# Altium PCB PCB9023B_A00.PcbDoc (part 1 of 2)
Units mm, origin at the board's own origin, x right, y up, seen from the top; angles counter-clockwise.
Board outline 30 x 45 mm, 4 copper layers (Top Layer, Signal Layer 2, Signal Layer 3, Bottom Layer), stack 1.606 mm thick; 75 components, 84 nets, 313 pads, 395 vias.
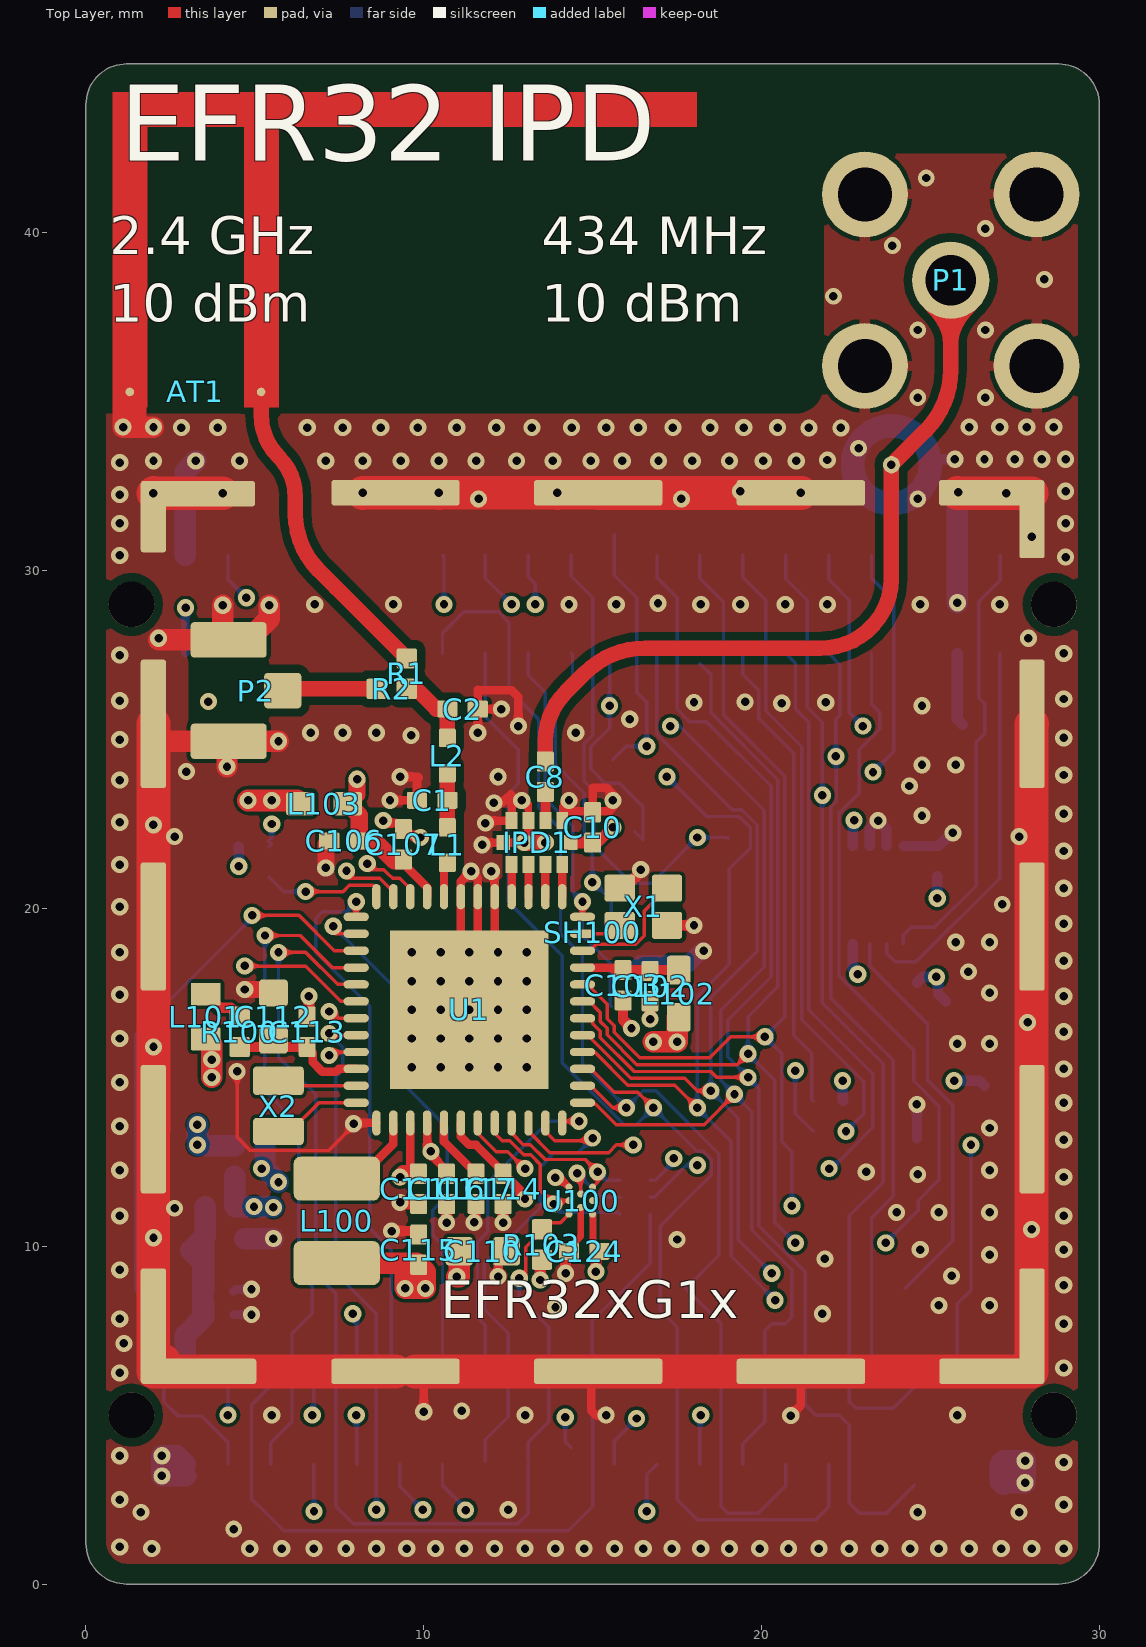
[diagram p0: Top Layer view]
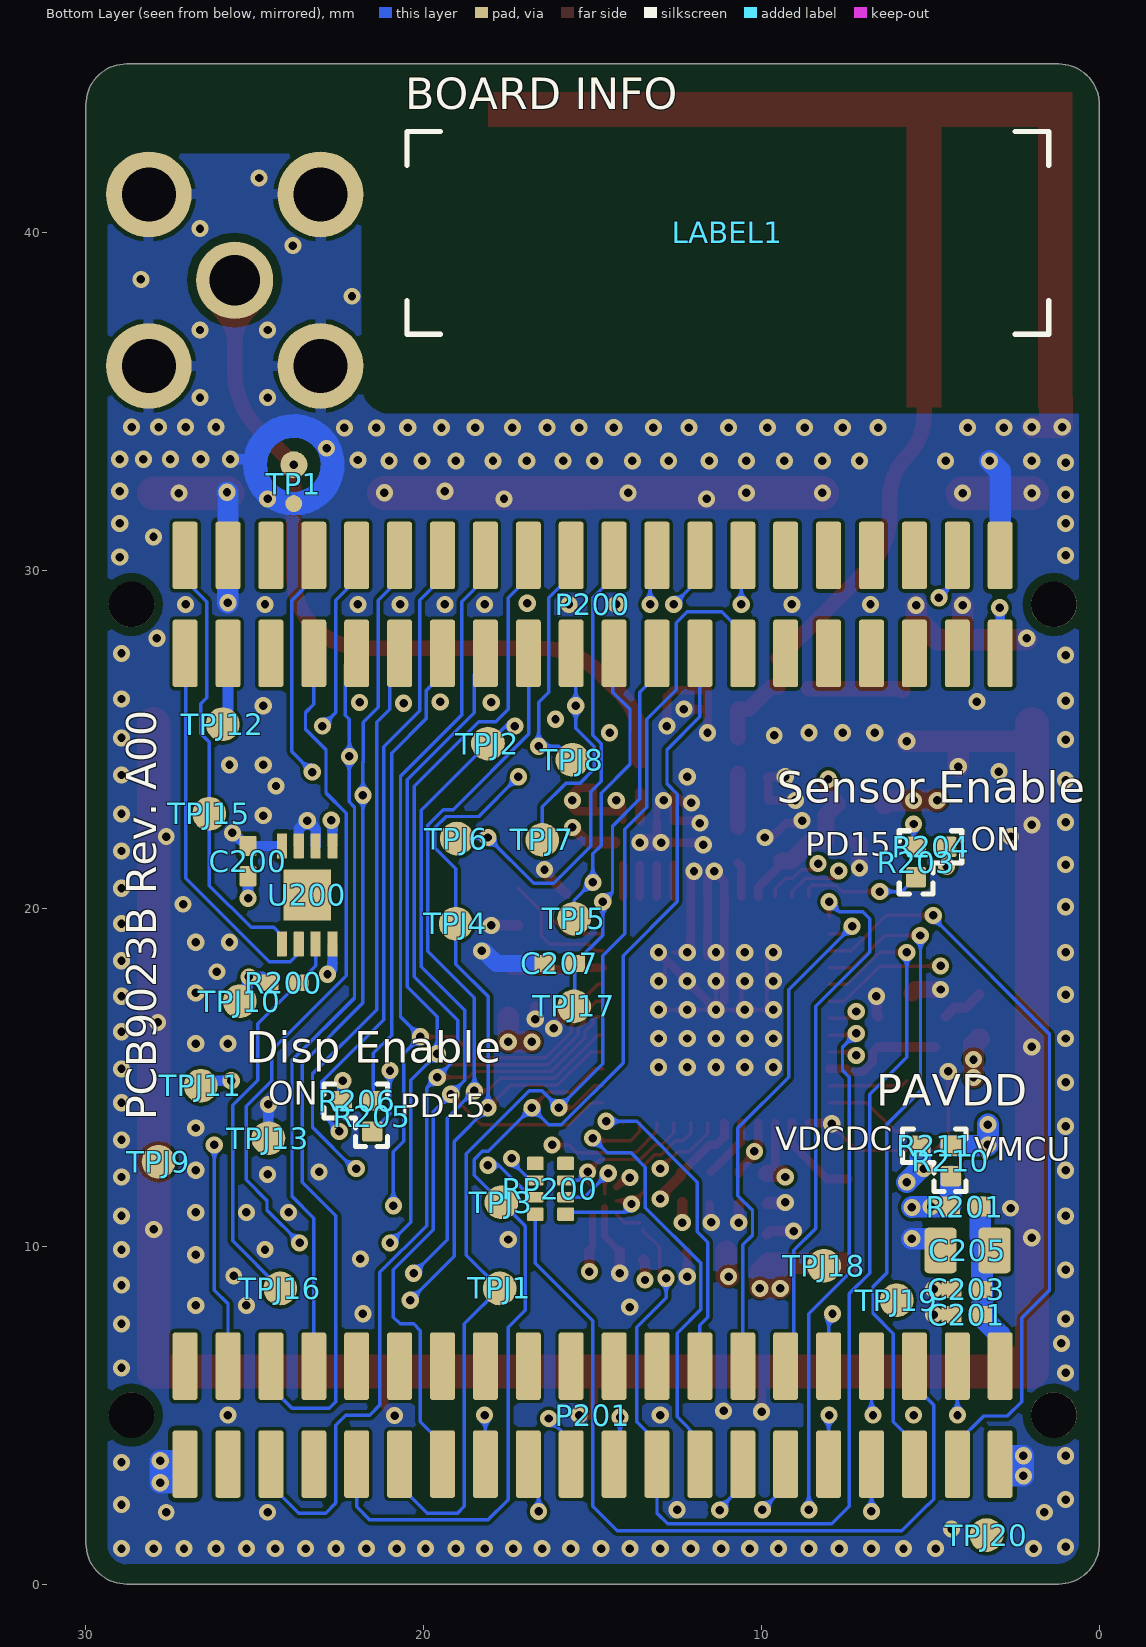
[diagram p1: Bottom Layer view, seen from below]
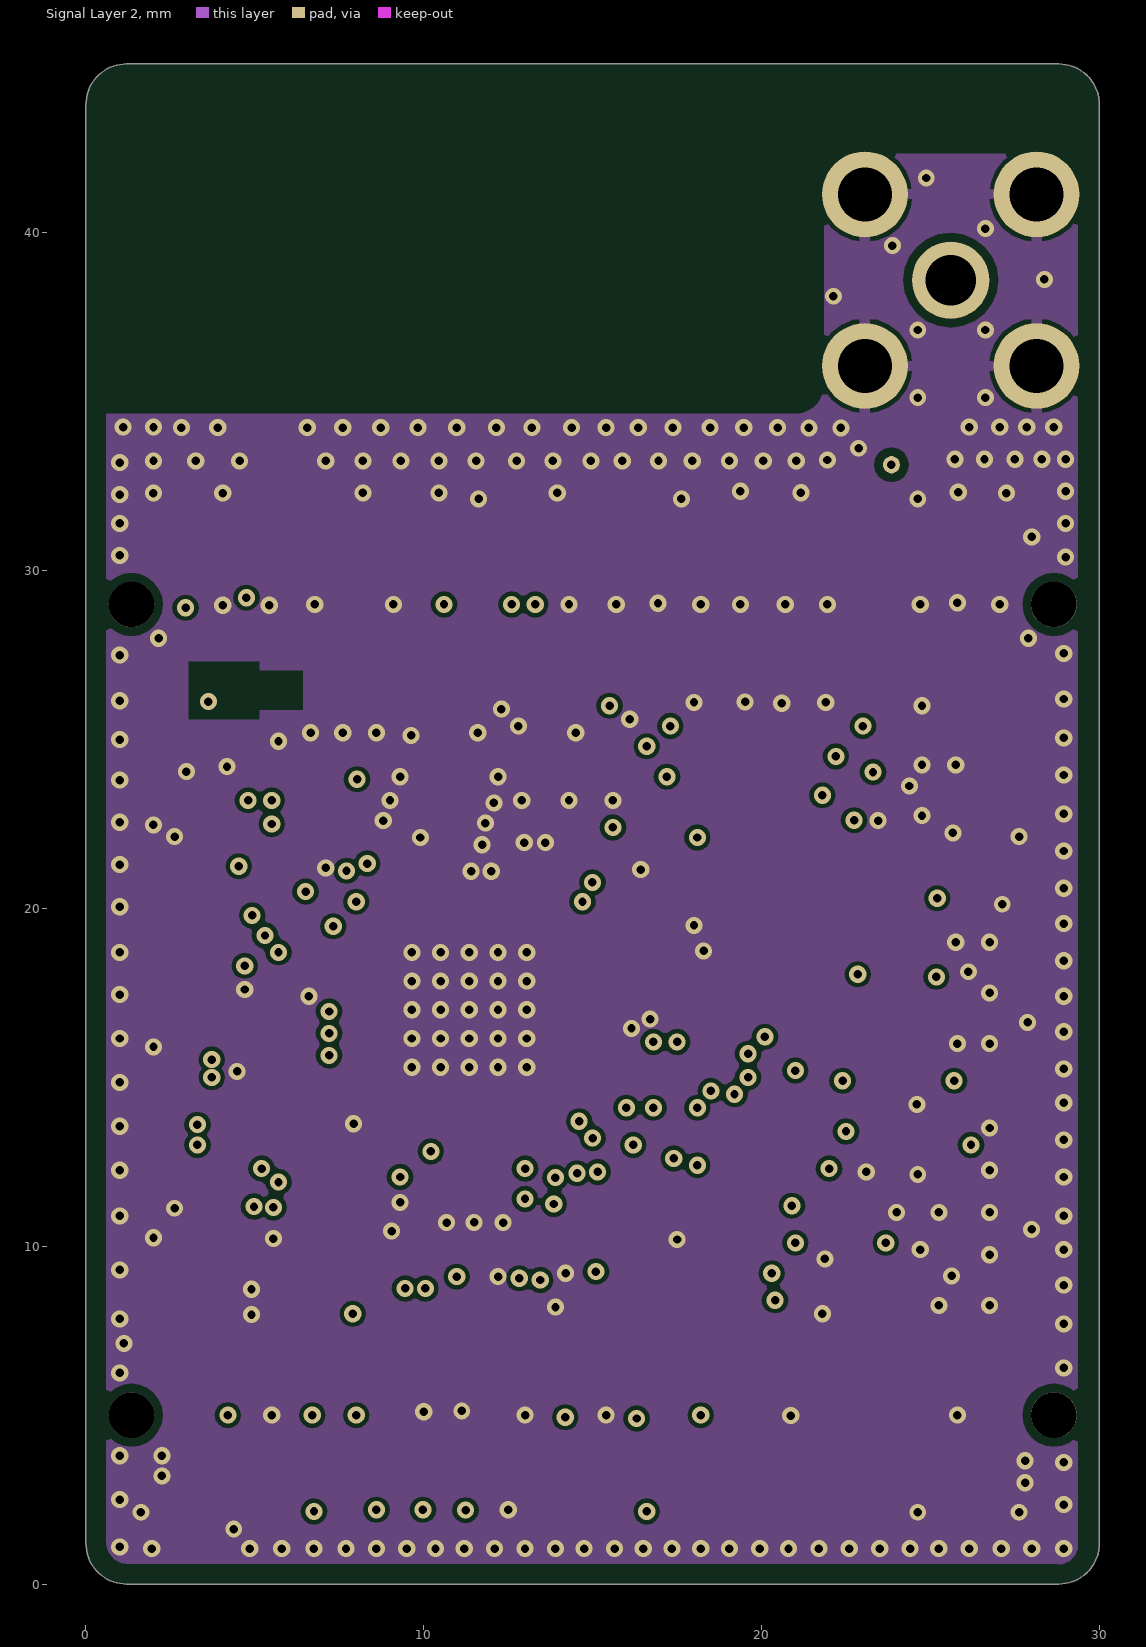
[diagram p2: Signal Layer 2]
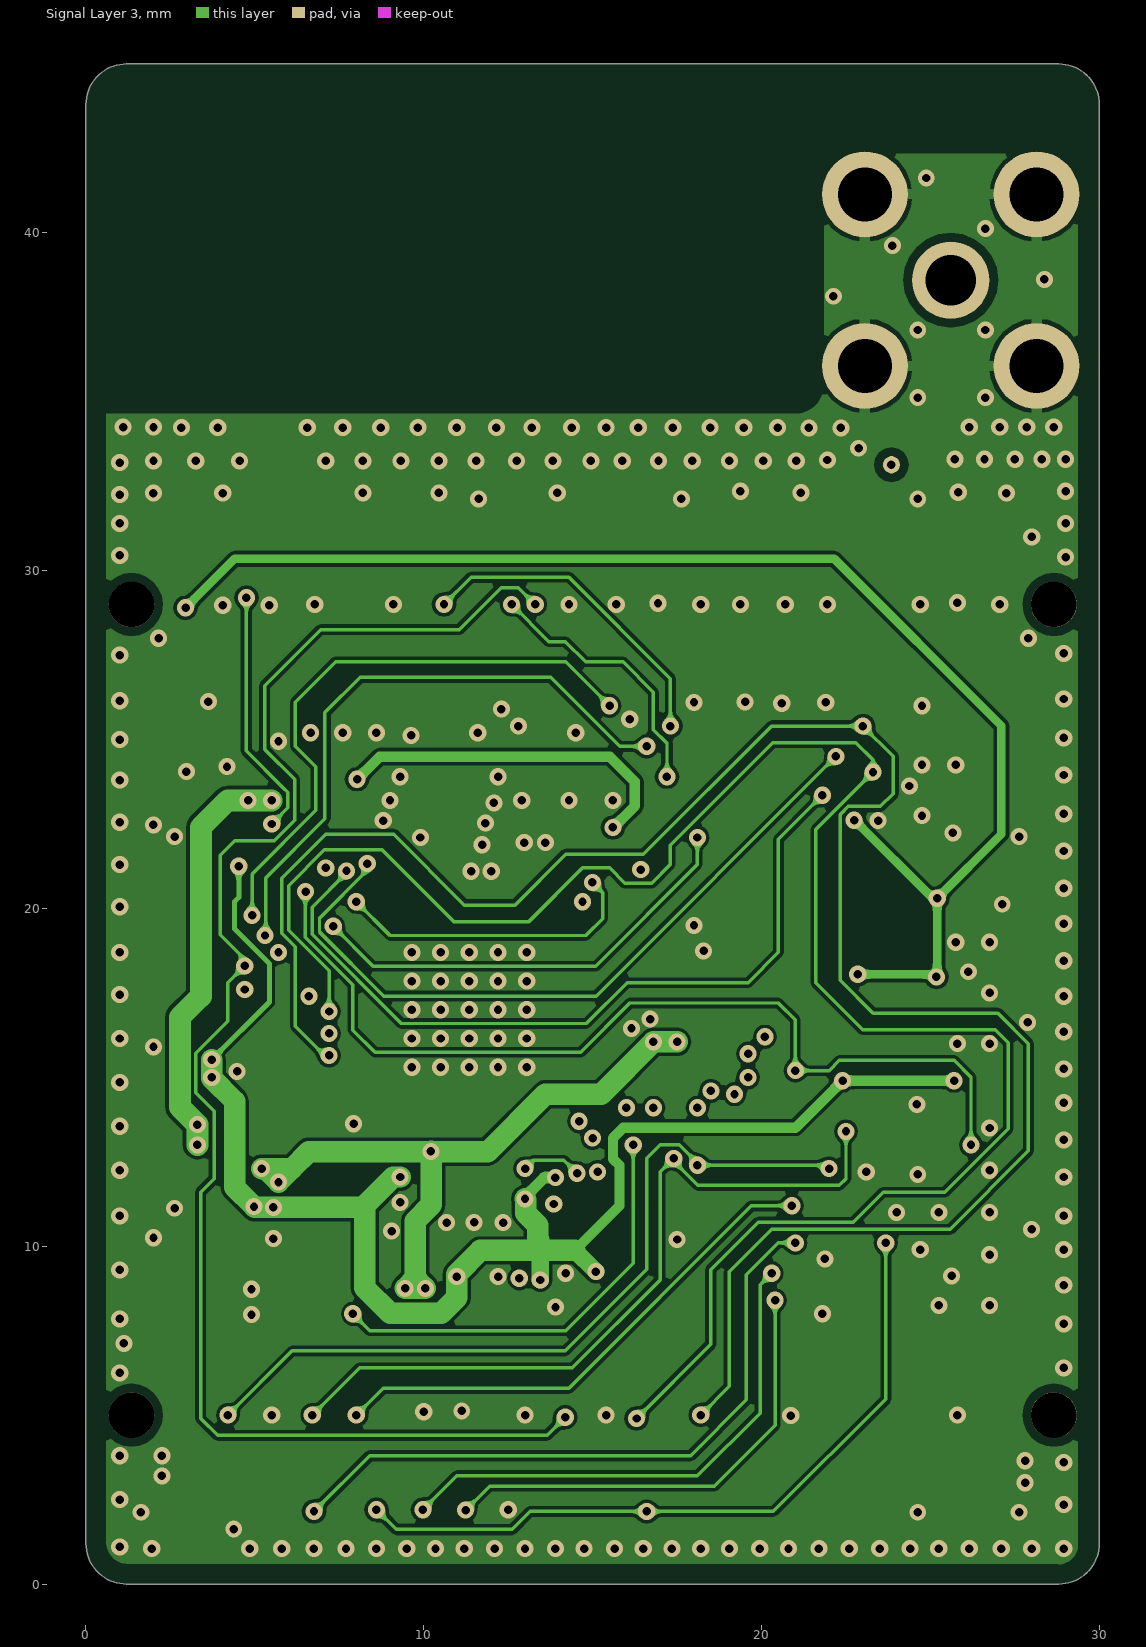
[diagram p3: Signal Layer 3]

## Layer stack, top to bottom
Top Solder: solder mask 0.01, Solder Resist, Dk 3.5
Top Layer: signal copper 0.035
Dielectric 1: core 0.3, FR-4, Dk 4.2
Signal Layer 2: signal copper 0.018
Dielectric 3: prepreg 0.9, Dk 4.2
Signal Layer 3: signal copper 0.018
Dielectric 2: core 0.3, FR-4, Dk 4.2
Bottom Layer: signal copper 0.035
Bottom Solder: solder mask 0.01, Solder Resist, Dk 3.5

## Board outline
0,1.2 ccw(c1.2,1.2) 1.2,0 28.8,0 ccw(c28.8,1.2) 30,1.2 30,43.8 ccw(c28.8,43.8) 28.8,45 1.2,45 ccw(c1.2,43.8) 0,43.8

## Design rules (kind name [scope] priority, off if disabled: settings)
Clearance stiching_distance [IsStitchingVia vs IsStitchingVia] p1: gap=1.5
Clearance radioPad-to-trace [(InComponent('P200') or InComponent('P201')) and IsPad vs IsTrack or IsVia] p2: gap=0.15
Clearance Clearance_to_Holes [InPadClass('NPTH')] p3: gap=0.254
Clearance Clearance_50Ohm [InNetClass('50Ohm') or InNet('50R_*')] p4: gap=0.25
Clearance Clerance_Polygon_GND3 [InNamedPolygon('GND_3')] p5: gap=0.127
Clearance Clerance_Polygon_GND2 [InNamedPolygon('GND_2')] p6: gap=0.127
Clearance Clerance_Polygon_GND1 [InNamedPolygon('GND_L2')] p7: gap=0.127
Clearance Clerance_Polygon_GND4 [InNamedPolygon('GND_4')] p8: gap=0.127
Clearance Clearance_General [All] p9: gap=0.102
ComponentClearance res_selector [InComponent('R2') or  InComponent('R203') or InComponent('R210') or InComponent('R205') vs InComponent('R1')  or InComponent('R204')  or InComponent('R211')  or     InComponent('R206')] p1: gap=-0.1 collisioncheckmode=3 verticalgap=-0.1 showdistances=FALSE
ComponentClearance [All] p2: gap=0.2 collisioncheckmode=3 verticalgap=0.2 showdistances=TRUE
HoleToHoleClearance HoleToHoleClearance_ANT1toPAD [Incomponent ('ANT1') vs ISpad] p1: gap=0 allowstackedmicrovias=TRUE
HoleToHoleClearance HoleToHoleClearance_U1toVIA_1 [InComponent ('U1') vs IsVia] p2: gap=0 allowstackedmicrovias=TRUE
HoleToHoleClearance [All] p3: gap=0.2 allowstackedmicrovias=TRUE
MinimumSolderMaskSliver [All] p1: minsoldermaskwidth=0.102
PolygonConnect PolygonConnect_SH100 [InComponent('SH100')] p1: connectstyle=Direct reliefconductorwidth=0.254 reliefentries=4 polygonreliefangle="90 Angle" airgapwidth=0.127
PolygonConnect PolygonConnect_P1 [InComponent('P1')] p2: connectstyle=Relief reliefconductorwidth=0.305 reliefentries=4 polygonreliefangle="90 Angle" airgapwidth=0.127
PolygonConnect Polygon_VIA_Connect [IsVia] p3: connectstyle=Direct reliefconductorwidth=0.254 reliefentries=4 polygonreliefangle="90 Angle" airgapwidth=0.254
PolygonConnect PolygonConnect_General [All] p4: connectstyle=NoConnect reliefconductorwidth=0.254 reliefentries=4 polygonreliefangle="90 Angle" airgapwidth=0.127
RoutingVias [All] p1: holewidth=0.25 width=0.508 viastyle="Through Hole" minholewidth=0.25 minwidth=0.508 maxholewidth=1 maxwidth=1.5
SilkToSilkClearance [All] p1: silktosilkclearance=0.102
SilkToSolderMaskClearance [IsPad] p1: minsilkscreentomaskgap=0.102 clearancetoexposedcopper=TRUE
SolderMaskExpansion [All] p1: expansion=0.051
Width 50ohm [InNetClass('50ohm')] p1: maxlimit=0.457 minlimit=0.457 preferedwidth=0.457
Width [All] p2: maxlimit=5.08 minlimit=0.102 preferedwidth=0.127
25 further rules are at their usual default settings.

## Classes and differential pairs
net class 50ohm: 50R_IFA 50R_R1 50R_SMA 50R_UFL N459294
pad class NPTH: P200-M1 P200-M2 P201-M1 P201-M2

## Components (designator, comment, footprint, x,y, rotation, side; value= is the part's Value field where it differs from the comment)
AT1 "INVERTED_F" ANT_INV_F_2.4_GHZ_17.3MM_MIR 0.79,34.84 r0 top locked net-tie
C1 "cfg" C0402_L 10.25,23.2 r0 top
C2 "cfg" C0402_L 11.15,25.9 r180 top
C8 "cfg" C0402_L 13.6,23.9 r90 top
C10 "cfg" C0402_L 15,22.4 r90 top
C102 "100P" C0402_L 16.7,17.7 r270 top
C103 "10P" C0402_L 15.9,17.725 r270 top
C106 "220N" C0402_L 7.65,22 r180 top
C107 "10P" C0402_L 9.4,21.9 r90 top
C110 "10U" C0603_L 11.75,9.85 r0 top
C111 "1U" C0402_L 9.848,11.7 r270 top
C112 "10U" C0603_L 5.55,16.8 r90 top
C113 "10N" C0402_L 6.548,16.35 r90 top
C114 "1U" C0402_L 12.35,11.7 r270 top
C115 "4U7" C0402_L 9.85,9.9 r90 top
C116 "100N" C0402_L 10.675,11.7 r270 top
C117 "1U" C0402_L 11.55,11.7 r270 top
C124 "100N" C0402_L 14.75,9.85 r180 top
C200 "100N" C0402_L 25.2,21.4 r90 bottom
C201 "100N" C0402_L 3.925,7.975 r0 bottom
C203 "100N" C0402_L 3.925,8.725 r0 bottom
C205 "10U" C0805_L 3.9,9.875 r0 bottom
C207 "100N" C0402_L 15.975,18.375 r0 bottom
Designator16 "Comment" PCB_SPEC_4_LAYER -81.197,100.739 r0 top
IPD1 "0868BM15G0027" EFR_IPD868M 13.35,21.95 r180 top
L1 "cfg" COIL_0402_L 10.7,21.875 r90 top
L2 "cfg" COIL_0402_L 10.7,24.525 r90 top
L100 "4U7" COIL_MUR_LQH3NP_1212 7.425,10.75 r270 top
L101 "CBF102WB" WURTH_CBF_0603 3.55,16.8 r90 top
L102 "BLM18AG601SN1" COIL_MUR_BLM18_0603 17.55,17.475 r90 top
L103 "BLM18AG601SN1" COIL_MUR_BLM18_0603 7.05,23.1 r0 top
LABEL1 "Comment" LABEL_4CORNERS_19.0X6.0 11,40 r180 bottom
P1 "SMA" TE_SMA_TH_1814832 25.6,38.6 r0 top locked
P2 "U.FL" HIROSE_U.FL-R-SMT-1 4.225,26.45 r270 top
P200 "SOCKET_2X20_1.27MM_SMD" SAM_SFC-120-T2-D-A-2X20_SNUM 15,29 r0 bottom locked
P201 "SOCKET_2X20_1.27MM_SMD" SAM_SFC-120-T2-D-A-2X20_SNUM 15,5 r0 bottom locked
R1 "0R" R0402_L 9.5,26.95 r90 top
R2 "0R" R0402_L 9.05,26.5 r180 top
R100 "1R" R0402_L 4.55,16.35 r270 top
R103 "330K" R0402_L 13.5,10.05 r90 top
R200 "10K" T_0402 24.15,17.8 r0 bottom
R201 "0R" R0402_L 3.975,11.175 r0 bottom
R203 "0R" R0402_L 5.425,21.375 r90 bottom
R204 "0R" R0402_L 4.975,21.825 r0 bottom
R205 "0R" R0402_L 21.525,13.85 r90 bottom
R206 "0R" R0402_L 21.975,14.3 r180 bottom
R210 "0R" R0402_L 4.4,12.525 r270 bottom
R211 "0R" R0402_L 4.85,12.975 r0 bottom
RP200 "100R" RES_MNR04-8 16.25,11.7 r90 bottom
SH100 "RF_SHIELD_FRAME_BMI-S-203-F" RF_SHIELD_FRAME_BMI-S-203-F_PCB4100 15,19.3 r0 top locked
TP1 "RF_TEST_POINT" "TP_INGUN_50_OHM_CLOSED openvia" 23.845,33.135 r180 bottom
TPJ1 "TPJ_SMD" TP_1.0_SMD 17.75,8.75 r90 bottom locked
TPJ2 "TPJ_SMD" TP_1.0_SMD 18.1,24.88 r90 bottom locked
TPJ3 "TPJ_SMD" TP_1.0_SMD 17.7,11.3 r90 bottom locked
TPJ4 "TPJ_SMD" TP_1.0_SMD 19.05,19.55 r90 bottom locked
TPJ5 "TPJ_SMD" TP_1.0_SMD 15.55,19.7 r90 bottom locked
TPJ6 "TPJ_SMD" TP_1.0_SMD 19.02,22.07 r90 bottom locked
TPJ7 "TPJ_SMD" TP_1.0_SMD 16.49,22.03 r90 bottom locked
TPJ8 "TPJ_SMD" TP_1.0_SMD 15.6,24.4 r90 bottom locked
TPJ9 "TPJ_SMD" TP_1.0_SMD 27.85,12.5 r90 bottom locked
TPJ10 "TPJ_SMD" TP_1.0_SMD 25.45,17.25 r90 bottom locked
TPJ11 "TPJ_SMD" TP_1.0_SMD 26.6,14.75 r90 bottom locked
TPJ12 "TPJ_SMD" TP_1.0_SMD 25.95,25.45 r90 bottom locked
TPJ13 "TPJ_SMD" TP_1.0_SMD 24.6,13.2 r90 bottom locked
TPJ15 "TPJ_SMD" TP_1.0_SMD 26.35,22.8 r90 bottom locked
TPJ16 "TPJ_SMD" TP_1.0_SMD 24.25,8.75 r90 bottom locked
TPJ17 "TPJ_SMD" TP_1.0_SMD 15.55,17.1 r90 bottom locked
TPJ18 "TPJ_SMD" TP_1.0_SMD 8.15,9.42 r90 bottom locked
TPJ19 "TPJ_SMD" TP_1.0_SMD 6,8.4 r90 bottom locked
TPJ20 "TPJ_SMD" TP_1.0_SMD 3.34,1.45 r90 bottom locked
U1 "EFR32-DUALBAND" QFN48_M050_SQ7.0_EP_SL_L 11.35,17 r180 top locked
U100 "MX25R8035F" BGA8_M040_1.24x1.75_WLCSP 14.648,11.35 r180 top
U200 "24AA024" TDFN8_M050_2.0x3.0_EP 23.45,20.4 r0 bottom
X1 "38.400 MHz" X_SSS_DSX211SH_2.05X1.65-4 16.5,20.05 r0 top
X2 "32.768kHz" X_MCS_CM8V-T1A 5.698,14.15 r90 top

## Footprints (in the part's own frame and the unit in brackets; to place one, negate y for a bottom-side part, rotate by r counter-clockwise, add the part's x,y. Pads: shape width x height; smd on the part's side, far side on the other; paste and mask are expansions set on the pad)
ANT_INV_F_2.4_GHZ_17.3MM_MIR [mil] "Antenna inverted F, 2.4 GHz, 17.3 mm (MIR)"
  round 10 smd paste-5 mask-5: 1(173,17.72) 2(20.01,17.72)
  Top Layer region: 0.36,367.2 681,367.2 681,327.07 193.36,327.07 193.36,0 153.36,0 153.36,327.07 40.36,327.07 40.36,0 20.36,0 0.36,0
BGA8_M040_1.24x1.75_WLCSP [mm] "BGA, 8 pin. U100"
  round 0.21 smd mask+0.051: A1(-0.35,0.4) A3(0.35,0.4) B2(0,0.2) C1(-0.35,0) C3(0.35,0) D2(0,-0.2) E1(-0.35,-0.4) E3(0.35,-0.4)
  body extent -0.63,-0.89 0.63,0.88, height 0.52
C0402_L [mm] "Chip Capacitor, 2-Leads, Body 1.0x0.5mm, IPC High Density"
  rrect20% 0.6x0.5 smd mask+0.051: 1(-0.45,0) 2(0.45,0)
  body extent -0.5,-0.25 0.5,0.25, height 0.6
C0603_L [mm] "Capacitor, 0603, High Density (C)"
  rrect25% 0.8x0.85 smd: 1(-0.7,0) 2(0.7,0)
  body extent -0.88,-0.48 0.87,0.48, height 0.95
C0805_L [mm] "Capacitor, 0805"
  rrect25% 0.95x1.35 smd: 1(-0.8,0) 2(0.8,0)
  body extent -1.1,-0.72 1.1,0.72, height 1.45
COIL_0402_L [mm] "COIL_0402_L"
  rrect20% 0.55x0.5 smd mask+0.051: 1(-0.525,0) 2(0.525,0)
  body extent -0.5,-0.25 0.5,0.25, height 0.6
COIL_MUR_BLM18_0603 [mm] "COIL_MUR_BLM18P_0603"
  rrect25% 0.85x0.7 smd mask+0.051: 1(-0.7,0) 2(0.7,0)
  body extent -0.88,-0.48 0.87,0.48, height 0.95
COIL_MUR_LQH3NP_1212 [mm] "COIL_MUR_LQH3NP_1212"
  rrect30% 1.3x2.55 smd mask+0.051: 1(-1.25,0) 2(1.25,0)
  body extent -1.6,-1.6 1.6,1.6, height 1.5
EFR_IPD868M [mm] "0868BM15G0027"
  rect 0.35x0.5 smd: 1(-0.75,-0.65) 2(-0.25,-0.65) 3(0.25,-0.65) 4(0.75,-0.65) 6(0.75,0.65) 7(0.25,0.65) 8(-0.25,0.65) 9(-0.75,0.65)
  rect 0.4x0.45 smd: 5(1,0) 10(-1,0)
  body extent -1,-0.63 1,0.62, height 1.5
HIROSE_U.FL-R-SMT-1 [mm] "COAX_HIROSE_U.FL_CL331-0471"
  rrect20% 1.05x1.1 smd mask+0.051: 1(0,1.6)
  rrect20% 1.05x2.25 smd mask+0.051: 2(-1.5,0) 3(1.5,0)
  Top Layer pour cut-out: -0.85,0.9 0.85,0.9 0.85,0.9 0.85,-1.2 -0.85,-1.2 -0.85,-1.2
  body extent -1.3,-1.55 1.3,1.3, height 0.9
LABEL_4CORNERS_19.0X6.0 [mm]
  silkscreen extent -9.5,-3 9.5,3
PCB_SPEC_4_LAYER [mm]
QFN48_M050_SQ7.0_EP_SL_L [mm] "QFN48_M050_SQ7.0_EP, SiLabs, High Density (C)"
  oval 0.75x0.25 smd: 1(-3.35,2.75) 2(-3.35,2.25) 3(-3.35,1.75) 4(-3.35,1.25) 5(-3.35,0.75) 6(-3.35,0.25) 7(-3.35,-0.25) 8(-3.35,-0.75) 9(-3.35,-1.25) 10(-3.35,-1.75) 11(-3.35,-2.25) 12(-3.35,-2.75) 25(3.35,-2.75) 26(3.35,-2.25) 27(3.35,-1.75) 28(3.35,-1.25) 29(3.35,-0.75) 30(3.35,-0.25) 31(3.35,0.25) 32(3.35,0.75) 33(3.35,1.25) 34(3.35,1.75) 35(3.35,2.25) 36(3.35,2.75)
  oval 0.25x0.75 smd: 13(-2.75,-3.35) 14(-2.25,-3.35) 15(-1.75,-3.35) 16(-1.25,-3.35) 17(-0.75,-3.35) 18(-0.25,-3.35) 19(0.25,-3.35) 20(0.75,-3.35) 21(1.25,-3.35) 22(1.75,-3.35) 23(2.25,-3.35) 24(2.75,-3.35) 37(2.75,3.35) 38(2.25,3.35) 39(1.75,3.35) 40(1.25,3.35) 41(0.75,3.35) 42(0.25,3.35) 43(-0.25,3.35) 44(-0.75,3.35) 45(-1.25,3.35) 46(-1.75,3.35) 47(-2.25,3.35) 48(-2.75,3.35)
  rrect50% 1.9x1.9 on Top Paste mask-0.805: 49(-1.15,1.15) 49(-1.15,-1.15) 49(1.15,1.15) 49(1.15,-1.15)
  rect 4.7x4.7 smd paste-4.7: 49(0,0)
  body extent -3.5,-3.5 3.5,3.5, height 0.9
R0402_L [mm] "Chip Resistor, 2-Leads, Body 1.0x0.5mm, IPC High Density"
  rrect20% 0.6x0.6 smd mask+0.051: 1(-0.45,0) 2(0.45,0)
  body extent -0.5,-0.25 0.5,0.25, height 0.6
RES_MNR04-8 [mm] "Chip resistor network 8pin"
  rrect20% 0.4x0.5 smd mask+0.051: 1(-0.75,-0.45) 4(0.75,-0.45) 5(0.75,0.45) 8(-0.75,0.45)
  rrect20% 0.3x0.5 smd mask+0.051: 2(-0.25,-0.45) 3(0.25,-0.45) 6(0.25,0.45) 7(-0.25,0.45)
  body extent -1,-0.4 1,0.4, height 0.5
RF_SHIELD_FRAME_BMI-S-203-F_PCB4100 [mm] "RF_SHIELD_FRAME_BMI-S-203-F"
  rrect20% 0.75x3.8 smd paste+0 mask+0.05: 1(-13.005,-5.835) 1(-13.005,0.165) 1(-13.005,6.165) 1(13.005,-5.835) 1(13.005,0.165) 1(13.005,6.165)
  rrect20% 0.75x3.4 smd paste+0 mask+0.05: 1(-13.005,-11.659) 1(13.005,-11.659)
  rrect20% 0.75x2.1 smd paste+0 mask+0.05: 1(-13.005,12.294)
  oval 0.75x0.254 smd paste+0 mask+0.05: 1(-13.004,12.994) 1(12.994,12.994) 1(12.994,12.994) 1(12.994,12.994)
  rrect20% 3.375x0.75 smd paste+0 mask+0.05: 1(-11.684,12.979)
  rrect20% 3.4x0.75 smd paste+0 mask+0.05: 1(-11.659,-13.005)
  rrect20% 3.8x0.75 smd paste+0 mask+0.05: 1(-5.835,-13.005) 1(-5.835,13.005) 1(0.165,-13.005) 1(0.165,13.005) 1(6.165,-13.005) 1(6.165,13.005)
  rrect20% 3.1x0.75 smd paste+0 mask+0.05: 1(11.811,-13.005)
  rrect20% 3.125x0.75 smd paste+0 mask+0.05: 1(11.811,13.005)
  rrect20% 0.75x2.3 smd paste+0 mask+0.05: 1(13.005,12.217)
  body extent -13.3,-13.3 13.3,13.3, height 5.5
SAM_SFC-120-T2-D-A-2X20_SNUM [mm]
  rrect20% 0.74x2 smd mask+0.05: 1(-12.065,1.45) 2(-12.065,-1.45) 3(-10.795,1.45) 4(-10.795,-1.45) 5(-9.525,1.45) 6(-9.525,-1.45) 7(-8.255,1.45) 8(-8.255,-1.45) 9(-6.985,1.45) 10(-6.985,-1.45) 11(-5.715,1.45) 12(-5.715,-1.45) 13(-4.445,1.45) 14(-4.445,-1.45) 15(-3.175,1.45) 16(-3.175,-1.45) 17(-1.905,1.45) 18(-1.905,-1.45) 19(-0.635,1.45) 20(-0.635,-1.45) 21(0.635,1.45) 22(0.635,-1.45) 23(1.905,1.45) 24(1.905,-1.45) 25(3.175,1.45) 26(3.175,-1.45) 27(4.445,1.45) 28(4.445,-1.45) 29(5.715,1.45) 30(5.715,-1.45) 31(6.985,1.45) 32(6.985,-1.45) 33(8.255,1.45) 34(8.255,-1.45) 35(9.525,1.45) 36(9.525,-1.45) 37(10.795,1.45) 38(10.795,-1.45) 39(12.065,1.45) 40(12.065,-1.45)
  round 1.35 hole 1.35 unplated paste-5.563 mask-5.563: M1(13.652,0) M2(-13.652,0)
  body extent -14.65,-1.58 14.65,2.25, height 4.57
T_0402 [mm] "Chip Capacitor, 2-Leads, Body 1.0x0.5mm, IPC High Density"
  rrect20% 0.6x0.5 smd mask+0.051: 1(-0.45,0) 2(0.45,0)
  body extent -0.5,-0.25 0.5,0.25, height 0.6
TDFN8_M050_2.0x3.0_EP [mm] "TDFN8_M050_2.0x3.0_EP"
  rrect20% 0.3x0.75 smd mask+0.051: 1(-0.75,-1.45) 2(-0.25,-1.45) 3(0.25,-1.45) 4(0.75,-1.45) 5(0.75,1.45) 6(0.25,1.45) 7(-0.25,1.45) 8(-0.75,1.45)
  rect 1.4x1.5 smd mask+0.051: 9(0,0)
  body extent -1,-1.5 1,1.5, height 1
TE_SMA_TH_1814832 [mm]
  round 2.286 hole 1.5: 1(0,0)
  round 2.54 hole 1.6: 2(-2.54,-2.54) 3(2.54,-2.54) 4(2.54,2.54) 5(-2.54,2.54)
  body extent -3.2,-3.2 3.2,3.2, height 9.5
TP_1.0_SMD [mm] "Test Point, 1.0 mm, SMD"
  round 1 smd paste-0.501: 1(0,0)
  body extent -0.2,-0.2 0.2,0.2, height 0.01
"TP_INGUN_50_OHM_CLOSED openvia" [mm] "TP_INGUN_50_OHM_CLOSED"
  round 0.8 / inner round 0.508 / far side round 0.508 hole 0.25 mask+0: 1(0,0)
  round 0.5 smd paste-0.255 mask-0.41: 2(0,-1.15)
  Top Layer lines w0.7: 0,-1.15 ccw(c0,0) -1.15,0 ccw(c0,0) 0,-1.15
WURTH_CBF_0603 [mm] "COIL_WURTH_CBF_0603_L (= L0603_0.8_L)"
  rrect10% 0.67x0.88 smd: 1(-0.665,0) 2(0.665,0)
  body extent -0.87,-0.48 0.87,0.48, height 0.95
X_MCS_CM8V-T1A [mm] "Crystal MCS CM8V-T1A (2 pin)"
  rrect25% 0.8x1.5 smd paste-0.15 mask+0.051: 1(-0.75,0)
  rrect25% 0.85x1.5 smd paste-0.15 mask+0.051: 2(0.75,0)
  body extent -1,-0.6 1,0.6, height 0.97
X_SSS_DSX211SH_2.05X1.65-4 [mm] "X_SSS_DSX211SH_2.05X1.65-4"
  rrect20% 0.9x0.8 smd mask+0.051: 1(-0.7,-0.55) 2(0.7,-0.55) 3(0.7,0.55) 4(-0.7,0.55)
  body extent -1.07,-0.87 1.07,0.87, height 0.5

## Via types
v1: diameter 0.508, hole 0.25, Top Layer to Bottom Layer, tented both sides, 364 vias
v2: diameter 0.5, hole 0.25, Top Layer to Bottom Layer, tented both sides, 31 vias

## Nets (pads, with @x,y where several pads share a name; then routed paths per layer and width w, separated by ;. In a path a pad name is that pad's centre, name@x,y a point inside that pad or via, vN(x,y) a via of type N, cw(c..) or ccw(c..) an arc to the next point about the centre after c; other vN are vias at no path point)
3V3: C200.1 P200.1 R200.2 TPJ10.1 U200.1 U200.8 | length 46
  Signal Layer 3 w0.254: v1(2.95,28.9) 4.4,30.35 22.15,30.35 27.1,25.4 27.1,22.2 v1(25.2,20.3) ; v1(22.738,22.613) 22.754,22.613 25.067,20.3 v1(25.2,20.3) ; v1(22.85,18.05) 25.15,18.05 v1@25.163,18.037 ; v1@25.2,18 v1(25.2,20.3)
  Bottom Layer w0.254: P200.1@2.935,27.55 2.935,28.885 v1(2.95,28.9)
  Bottom Layer w0.305: U200.8@22.7,18.95 22.7,18.2 v1(22.85,18.05) ; U200.1@22.7,21.85 22.7,22.575 v1(22.738,22.613) ; R200.2@24.6,17.8 24.775,17.975 v1(25.175,17.975) 25.225,17.925 25.225,17.475 TPJ10.1@25.45,17.25 ; v1(25.2,20.3) C200.1@25.2,20.95
5V: P200.37 TPJ12.1 | length 2.2
  Bottom Layer w0.33: P200.37@25.795,27.55 25.795,25.605 TPJ12.1@25.95,25.45
50R_IFA: AT1.1 R1.2 | length 9.4
  Top Layer w0.457: AT1.1@5.184,35.29 5.184,34.628 ccw(c6.963,34.628) 5.704,33.371 ; 5.706,33.369 cw(c4.513,32.176) 5.709,33.366 cw(c4.513,32.176) 6.2,32.176 6.2,31.69 ccw(c8.59,31.69) 6.9,30 7.4,29.5 R1.2@9.5,27.4
50R_R1: C2.2 L2.2 R1.1 R2.1 | length 2.3
  Top Layer w0.457: R1.1@9.525,26.55 9.725,26.55 10.375,25.9 C2.2@10.7,25.9 L2.2@10.7,25.05
50R_SMA: C8.2 P1.1 TP1.1 | length 22.9
  Top Layer w0.457: C8.2@13.6,24.35 13.6,24.951 cw(c15.649,24.951) 14.2,26.4 14.764,26.964 cw(c16.56,25.168) 16.56,27.708 21.742,27.708 ccw(c21.772,29.78) 23.845,29.75 TP1.1@23.845,33.135 24.856,34.146 ccw(c23.06,35.942) 25.6,35.942 P1.1@25.6,38.6
50R_UFL: P2.1 R2.2 | length 2.8
  Top Layer w0.457: P2.1@5.825,26.45 5.875,26.5 R2.2@8.6,26.5
BOARD_ID_SCL: P200.39 U200.6 | length 11.4
  Bottom Layer w0.102: U200.6@23.7,18.95 23.7,18.676 23.953,18.423 24.573,18.423 27.05,20.9 27.05,27.535 P200.39@27.065,27.55
BOARD_ID_SDA: P200.40 TPJ15.1 U200.5 | length 13.2
  Bottom Layer w0.102: U200.5@24.2,18.95 24.2,19.2 24.438,19.438 25.113,19.438 26.35,20.675 TPJ15.1@26.35,22.8 26.35,24.927 26.602,25.18 26.602,26.061 26.425,26.238 26.425,29.075 27.065,29.715 P200.40@27.065,30.45
BOARD_ID_WP: R200.1 TPJ16.1 U200.7 | length 11.8
  Bottom Layer w0.102: U200.7@23.2,18.95 23.2,18.3 R200.1@23.7,17.8 24.912,16.588 24.912,14.912 25.656,14.168 25.656,10.156 TPJ16.1@24.25,8.75
EXP_HEADER4: P200.29 P201.4 RP200.7 | length 43.5
  Signal Layer 3 w0.102: v1(4.2,5) 6.1,6.9 14.187,6.9 16.6,9.313 16.6,12.6 17.006,13.006 17.568,13.006 18.1,12.475 v1(18.1,12.4) 21.9,12.4 v1(22,12.3)
  Bottom Layer w0.102: v1(4.2,5) 4.205,5.005 P201.4@4.205,6.45 ; RP200.7@16.7,11.45 16.825,11.45 17.775,12.4 v1(18.1,12.4) ; P200.29@20.715,27.55 21.005,27.26 21.005,25.895 21.394,25.506 21.394,17.006 23.293,15.107 23.293,13.519 22.075,12.3 v1(22,12.3)
EXP_HEADER6: P201.6 RP200.8 | length 24.3
  Bottom Layer w0.102: P201.6@5.475,6.45 5.475,5.875 4.9,5.3 4.9,2.514 5.065,2.349 5.084,2.349 5.855,1.578 14.278,1.578 15,2.3 15,4.825 14.994,4.832 14.994,7.794 16.7,9.5 RP200.8@16.7,10.95
EXP_HEADER8: P200.28 P201.8 RP200.6 | length 43.9
  Signal Layer 3 w0.102: v1(6.7,5) 8.1,6.4 14.4,6.4 17,9 17,12.2 v1(17.4,12.6) 17.4,12.513 18.113,11.8 22.3,11.8 22.5,12 v1(22.5,13.4)
  Bottom Layer w0.102: v1(6.7,5) 6.745,5.045 P201.8@6.745,6.45 ; RP200.6@16.7,11.95 16.85,11.95 17.4,12.5 v1(17.4,12.6) ; P200.28@19.445,30.45 19.445,29.806 20.123,29.128 20.123,25.852 21.19,24.785 21.19,16.71 23.025,14.875 23.025,13.925 v1(22.5,13.4)
FLASH_MISO: RP200.1 U1.44 U100.C3 | length 6
  Top Layer w0.102: U1.44@12.1,13.65 12.098,13.35 12.325,13.123 12.55,13.123 12.966,12.706 13.168,12.706 13.454,12.42 13.454,11.646 v1(13.85,11.25) 13.95,11.35 U100.C3@14.298,11.35
  Bottom Layer w0.102: v1@13.824,11.224 14.045,11.003 15.747,11.003 RP200.1@15.8,10.95
FLASH_MOSI: RP200.2 U1.43 U100.D2 | length 6.2
  Top Layer w0.102: U1.43@11.598,13.65 11.598,13.35 12.148,12.8 12.484,12.8 12.984,12.3 v1(13,12.3) ; v1(14.538,12.161) 14.648,12.051 U100.D2@14.648,11.55
  Signal Layer 3 w0.102: v1(13,12.3) 13.25,12.55 14.149,12.55 v1(14.538,12.161)
  Bottom Layer w0.102: v1(14.538,12.161) 15.249,11.45 RP200.2@15.8,11.45
FLASH_SCLK: RP200.3 U1.45 U100.E1 | length 4.6
  Top Layer w0.102: U1.45@12.6,13.65 12.598,13.362 12.95,13.01 13.152,13.01 13.595,12.567 14.781,12.567 v1(15.148,12.2) 15.148,11.9 U100.E1@14.998,11.75
  Bottom Layer w0.102: v1(15.148,12.2) 15.398,11.95 RP200.3@15.8,11.95
FLASH_SCS: P201.17 R103.2 U1.29 U100.A3 | length 35.9
  Top Layer w0.102: v1(5.7,18.7) 6.498,18.7 7.448,17.75 U1.29@8,17.75 ; v1(12.826,9.05) 13.015,9.24 13.015,9.965 13.5,10.45 R103.2@13.5,10.5 ; R103.2@13.6,10.7 14.048,10.7 U100.A3@14.298,10.95
  Bottom Layer w0.102: v1(5.7,18.7) 5.7,15.6 6.8,14.5 6.8,9.2 7.4,8.6 7.4,2.3 7.919,1.781 12.781,1.781 13.095,2.095 P201.17@13.095,3.55 ; v1(12.826,9.05) 12.826,8.474 13.7,7.6 13.7,4.8 13.095,4.195 P201.17@13.095,3.635
GND: AT1.2 C1.1 C2.1 C10.2 C102.2 C103.2 C106.2 C107.2 C110.2 C111.2 C112.2 C113.2 C114.2 C115.2 C116.2 C117.2 C124.2 C200.2 C201.2 C203.2 C205.2 C207.2 IPD1.1 IPD1.3 IPD1.4 IPD1.5 P1.2 P1.3 P1.4 P1.5 P2.2 P2.3 P200.2 P200.38 P201.1 P201.39 SH100.1 TP1.2 TPJ13.1 U1.17 U1.18 U1.19 U1.37 U1.49@11.35,17 U100.B2 U200.2 U200.3 U200.4 X1.2 X1.4 | length 175.4
  Top Layer w0.102: v1(4.475,15.175) 4.475,13.225 4.865,12.835 7.183,12.835 v1@7.998,13.65 ; U1.49@9.848,18.7 9.848,17 U1.49@10.598,17 ; U1.49@10.598,17.85 U1.49@10.598,17 ; v1(11.348,17.85) v1(11.348,17) ; U1.49@12.098,18.7 U1.49@12.648,18.7 ; U1.49@12.848,17 U1.49@11.35,17 v1(11.348,17) ; U1.49@12.848,17.85 12.848,18.5 U1.49@12.848,18.7 ; U1.49@10.598,17 v1(11.348,17)
  Top Layer w0.2: v1(11.726,21.886) 11.726,21.784 11.656,21.854 v1@11.752,21.95 ; v1(12.9,23.2) 13,23.2 13.1,23.1 IPD1.3@13.1,22.6 ; IPD1.1@14.1,22.6 14.1,23 v1(14.3,23.2)
  Top Layer w0.203: C124.2@14.198,9.85 14.648,10.3 U100.B2@14.648,11.15
  Top Layer w0.254: v1@7.998,13.65 U1.37@8.598,13.65 ; v1(8.8,22.6) 8.877,22.523 9.277,22.523 9.7,22.1 v1(9.9,22.1) ; v1(9,23.2) C1.1@9.8,23.2 9.8,23.825 9.85,23.875 9.825,23.9 v1(9.3,23.9) ; SH100.1@9.165,6.295 9.756,6.295 10,6.051 v1(10,5.1) ; 11.098,19.848 U1.19@11.098,20.35 ; U1.49@11.1,17.25 U1.19@11.1,20.35 11.1,20.8 v1(11.4,21.1) 11.6,20.9 U1.18@11.6,20.35 ; v1(11.348,17) U1.49@12.848,18.5 ; v1(11.49,10.704) 11.538,10.752 11.538,11.238 C117.2@11.55,11.25 ; 11.594,26.459 11.6,26.459 ; U1.18@11.598,20.35 11.598,19.348 11.6,19.35 U1.49@11.6,18.6 ; v1(11.6,25.2) C2.1@11.6,25.9 ; 11.6,26.474 11.6,26.459 ; v1@11.752,21.95 IPD1.5@12.35,21.95 13.097,21.95 IPD1.3@13.097,22.58 ; v1(11.825,22.525) 11.9,22.6 IPD1.4@12.6,22.6 12.6,23.35 12.575,23.375 12.326,23.126 v1(12.076,23.126) ; v1(12,21.1) 12.1,21 U1.17@12.1,20.35 ; U1.49@12.098,18.7 12.098,19.348 U1.17@12.1,20.35 ; C110.2@12.198,9.85 12.238,9.81 12.2,9.772 v1(12.2,9.1) ; v1(12.3,25.9) C2.1@11.6,25.9 ; v1(12.8,25.4) 12.8,26.261 12.602,26.459 11.6,26.459 ; v1@14.4,23.2 14.45,23.2 14.124,22.874 14.976,22.874 C10.2@15,22.85 ; SH100.1@15.165,6.295 14.963,6.093 14.963,5.126 15.089,5 v1(15.4,5) ; v1(15.6,23.2) 15.6,22.989 15.488,22.877 15.027,22.877 C10.2@15,22.85 ; v1@15.605,23.199 15.605,23.373 15.407,23.572 15,23.572 C10.2@15,22.85 ; v1(20.863,4.988) 21.165,5.29 SH100.1@21.165,6.295 ; C2.1@11.6,25.9 11.6,26.459
  Top Layer w0.305: v1(0.998,21.3) v1@0.998,21.35 ; C113.2@6.548,16.8 6.6,16.852 v1(6.6,17.4) ; v1(9.05,10.45) C115.2@9.747,10.45 ; C115.2@9.747,10.451 C115.2@9.848,10.35 ; v1(10.675,10.7) C116.2@10.675,11.25 ; v1(12.348,10.7) C114.2@12.348,11.3 ; v1@14.198,9.25 C124.2@14.198,9.85 ; X1.4@15.8,20.45 16.426,21.076 v1(16.426,21.151) ; C103.2@15.9,17.1 15.9,16.7 v1(16.15,16.45) ; v1(16.701,16.726) C102.2@16.701,17.099 ; X1.2@17.2,19.5 v1(18,19.5) ; SH100.1@28,30.95 v1(28,31) ; v1(9.298,11.3) 9.348,11.25 C111.2@9.848,11.25 9.798,11.3 v1(9.298,11.3)
  Top Layer w0.5: v1(4.7,17.6) 5.45,17.6 C112.2@5.55,17.5
  Top Layer w0.508: v1(7.1,21.201) 7.104,21.205 7.104,21.904 C106.2@7.2,22 ; v1(12.975,21.95) v1(13.6,21.95)
  Top Layer w0.635: v1(2,34.25) 1.475,34.25 ; v1@2.15,27.95 P2.2@4.075,27.95 ; SH100.1@2.3,24.95 P2.3@4.225,24.95 ; v1(4.05,28.975) 4.05,28.125 P2.2@4.225,27.95 4.8,27.95 5.425,28.575 v1(5.425,28.975) ; v1(4.175,24.2) 4.175,24.85 4.15,24.875 P2.3@4.225,24.95 ; v1(5.7,24.95) P2.3@4.225,24.95 ; 1.475,34.25 1.475,35.113 AT1.2@1.298,35.29 1.1,35.092 v1(1.1,34.25) 1.475,34.25
  Top Layer w1: SH100.1@1.995,6.296 SH100.1@1.995,13.465 ; SH100.1@1.995,13.465 v1(1.996,22.475) SH100.1@1.995,25.465 ; SH100.1@2.006,32.305 v1(1.996,32.294) v1(4.05,32.294) ; SH100.1@2.3,6.6 1.996,6.296 SH100.1@9.165,6.295 ; v1(8.2,32.3) 8.205,32.305 SH100.1@9.165,32.305 SH100.1@10.445,32.305 ; SH100.1@9.756,6.295 SH100.1@15.165,6.295 SH100.1@21.02,6.295 ; v1(10.45,32.3) SH100.1@10.445,32.305 ; v1(13.95,32.3) SH100.1@13.955,32.305 ; SH100.1@19.324,32.3 15.17,32.3 SH100.1@15.165,32.305 SH100.1@13.955,32.305 ; SH100.1@19.428,32.3 21.16,32.3 v1(21.165,32.305) SH100.1@21.176,32.294 ; SH100.1@21.165,6.295 SH100.1@27.994,6.295 ; SH100.1@25.8,32.3 25.805,32.294 v1(27.25,32.294) SH100.1@27.994,32.294 ; SH100.1@27.994,6.296 v1(27.994,10.5) 27.994,25.454 SH100.1@28.005,25.465 ; SH100.1@10.445,32.305 SH100.1@13.955,32.305
  Bottom Layer w0.254: C203.2@4.363,8.663 4.425,8.725 v1(4.9,8.725) ; C201.2@4.375,7.975 v1(4.9,7.975) 4.975,7.975 4.975,7.925 v1@4.963,7.913
  Bottom Layer w0.305: U200.2@23.2,21.85 23.2,22.35 v1(23.45,22.6) 23.7,22.35 U200.3@23.7,21.85 ; U200.4@24.2,21.85 C200.2@25.2,21.85 25.25,21.85 25.638,22.238 v1(25.663,22.238) ; TPJ13.1@24.6,13.2 v1(24.6,14.2) ; 24.995,33.135 25.16,33.3 v1(25.725,33.3)
  Bottom Layer w0.508: C207.2@16.425,18.375 17.85,18.375 18.218,18.743 v1(18.285,18.743)
  Bottom Layer w0.635: P201.1@2.9,3.25 2.95,3.2 v1(2.25,3.2) v1(2.25,3.8) 2.685,3.8 P201.1@2.935,3.55 ; P200.2@2.935,30.45 2.935,32.935 v1(3.25,33.25) ; C205.2@4.7,10.225 v1(5.55,10.225) ; v1(25.8,29.05) 25.8,30.445 P200.38@25.795,30.45 25.795,32.29 v1(25.825,32.319) ; P201.39@27.065,3.55 27.7,3.55 v1(27.8,3.65) ; P201.39@27.065,3.55 27.165,3.65 v1(27.8,3.65) ; P201.39@27.065,3.55 27.065,3.035 27.15,2.95 27.2,3 v1(27.8,3) v1(27.8,3.65)
  other v1: 1.948,1.05 4.848,1.05 5.798,1.05 6.748,1.05 7.698,1.05 8.598,1.05 9.498,1.05 10.348,1.05 11.198,1.05 12.098,1.05 12.998,1.05 13.898,1.05 14.748,1.05 15.648,1.05 16.498,1.05 17.348,1.05 18.198,1.05 19.048,1.05 19.948,1.05 20.798,1.05 21.698,1.05 22.598,1.05 23.498,1.05 24.398,1.05 25.248,1.05 26.148,1.05 27.098,1.05 27.998,1.05 28.948,1.05 0.998,1.1 12.5,2.2 28.948,2.35 0.998,2.5 28.948,3.6 0.998,3.8 5.5,5 13,5 25.8,5 0.998,6.25 28.948,6.4 28.948,7.7 0.998,7.85 21.8,8 13.9,8.2 25.25,8.25 26.75,8.25 28.948,8.85 14.2,9.2 0.998,9.3 26.75,9.75 24.7,9.9 28.948,9.9 17.5,10.2 2,10.25 0.998,10.9 28.948,10.9 24,11 25.25,11 26.75,11 28.948,12.05 23.1,12.2 0.998,12.25 26.75,12.25 28.948,13.15 26.75,13.5 0.998,13.55 7.923,13.625 28.948,14.25 0.998,14.85 28.948,15.25 9.648,15.3 10.498,15.3 11.348,15.3 12.198,15.3 13.048,15.3 2,15.9 25.8,16 26.75,16 0.998,16.15 9.648,16.15 10.498,16.15 11.348,16.15 12.198,16.15 13.048,16.15 28.948,16.35 9.648,17 10.498,17 12.198,17 13.048,17 28.948,17.4 0.998,17.45 26.75,17.5 9.648,17.85 10.498,17.85 12.198,17.85 13.048,17.85 28.948,18.45 0.998,18.7 9.648,18.7 10.498,18.7 11.348,18.7 12.198,18.7 13.048,18.7 25.75,19 26.75,19 28.948,19.55 0.998,20.05 28.948,20.6 28.948,21.7 0.998,22.55 24.75,22.75 28.948,22.8 0.998,23.8 12.2,23.9 28.948,23.95 2.975,24.05 24.75,24.25 25.75,24.25 0.998,25 28.948,25.05 6.65,25.2 7.6,25.2 8.6,25.2 14.5,25.2 16.1,25.6 24.75,26 18,26.1 20.599,26.076 21.9,26.1 19.513,26.113 0.998,26.15 28.948,26.2 0.998,27.5 28.948,27.55 2.149,27.999 27.9,28 6.775,29 9.1,29 14.3,29 15.7,29 18.2,29 19.375,29 20.7,29 21.95,29 24.7,29 27.05,29 16.935,29.035 29,30.4 1,30.45 1,31.4 29,31.4 1,32.25 19.376,32.352 29,32.35 1,33.2 2,33.25 4.55,33.25 7.1,33.25 8.2,33.25 9.325,33.25 10.45,33.25 11.55,33.25 12.75,33.25 13.825,33.25 14.95,33.25 15.875,33.25 16.95,33.25 17.95,33.25 19.05,33.25 20.05,33.25 21.025,33.25 21.95,33.275 26.6,33.3 27.5,33.3 28.3,33.3 29,33.3 21.4,34.225 22.35,34.225 2.825,34.233 3.9,34.233 6.55,34.233 7.6,34.233 8.725,34.233 9.825,34.233 10.975,34.233 12.15,34.233 13.2,34.233 14.375,34.233 15.4,34.233 16.35,34.233 17.375,34.233 18.475,34.233 19.475,34.233 20.475,34.233 26.15,34.25 27.05,34.25 27.85,34.25 28.65,34.25
  other v2: 4.375,1.625 1.625,2.125 24.625,2.125 27.625,2.125 11.125,5.125 1.125,7.125 25.625,9.125 21.875,9.625 2.625,11.125 24.625,12.125 27.875,16.625 26.125,18.125 27.125,20.125 2.625,22.125 27.625,22.125 24.375,23.625 9.625,25.125 3.625,26.125 11.625,32.125 17.625,32.125 24.625,32.125 22.875,33.625 24.625,35.125 26.625,35.125 24.625,37.125 26.625,37.125 22.125,38.125 28.375,38.625 23.875,39.625 26.625,40.125 24.875,41.625
LFXTAL_N: U1.36 X2.1 | length 2.7
  Top Layer w0.102: X2.1@5.698,13.4 6.048,13.4 6.898,14.25 U1.36@8,14.25
LFXTAL_P: U1.35 X2.2 | length 2.4
  Top Layer w0.102: X2.2@5.698,14.9 5.848,14.75 U1.35@8,14.75
N458648: U1.10 X1.3 | length 3.7
  Top Layer w0.102: U1.10@14.7,18.75 14.925,18.75 15.11,18.935 16.272,18.935 16.525,19.188 16.525,19.925 X1.3@17.2,20.6
N458652: U1.11 X1.1 | length 1.6
  Top Layer w0.102: U1.11@14.698,19.25 U1.11@14.7,19.25 15.748,19.25 X1.1@16.148,19.65
N458798: C102.1 C103.1 L102.2 U1.9 | length 2.9
  Top Layer w0.254: U1.9@14.7,18.25 15.65,18.25
  Top Layer w0.305: 15.65,18.175 C103.1@15.9,18.175 C102.1@16.475,18.175 ; C102.1@16.45,18.15 C102.1@16.475,18.175 ; L102.2@17.4,18.3 L102.2@17.275,18.175 ; L102.2@17.425,18.175 L102.2@17.275,18.175 ; C102.1@16.475,18.175 L102.2@17.275,18.175
N459084: IPD1.7 U1.15 | length 1
  Top Layer w0.25: U1.15@13.1,20.35 IPD1.7@13.1,21.3
N459088: IPD1.6 U1.16 | length 1
  Top Layer w0.25: U1.16@12.6,20.35 IPD1.6@12.6,21.3
N459294: C1.2 L1.2 L2.1 | length 1.6
  Top Layer w0.457: L1.2@10.7,22.4 C1.2@10.7,23.2 L2.1@10.7,24
N459368: L1.1 U1.20 | length 1
  Top Layer w0.25: U1.20@10.6,20.35 10.6,21.25 L1.1@10.7,21.35
N459726: L101.2 R100.1 | length 1.3
  Top Layer w0.305: L101.2@3.55,17.465 3.958,17.057 4.293,17.057 R100.1@4.55,16.8
N459730: C112.1 C113.1 R100.2 U1.34 | length 3.7
  Top Layer w0.254: C113.1@6.548,15.9 6.715,15.733 6.715,15.45 6.998,15.167 7.398,15.167 7.481,15.25 U1.34@8,15.25
  Top Layer w0.305: 4.85,15.9 C113.1@6.548,15.9
N460020: C117.1 U1.41 | length 1.8
  Top Layer w0.254: U1.41@10.598,13.65 10.598,13.1 C117.1@11.498,12.2
N460222: L100.1 U1.38 | length 2.7
  Top Layer w0.254: L100.1@7.438,11.992 8.067,11.992 9.098,13.023 U1.38@9.1,13.65
N16660570: IPD1.9 U1.13 | length 1
  Top Layer w0.25: U1.13@14.1,20.35 IPD1.9@14.1,21.3
N16660574: IPD1.8 U1.14 | length 1
  Top Layer w0.25: U1.14@13.6,20.35 IPD1.8@13.6,21.3
N16660958: C8.1 IPD1.2 | length 0.8
  Top Layer w0.3: IPD1.2@13.6,22.6 C8.1@13.6,23.45
PAVDD: L103.1 R210.1 R211.1 | length 15.6
  Top Layer w0.65: v1(4.8,23.2) v1(5.5,23.2) 6.25,23.2 L103.1@6.35,23.1
  Signal Layer 3 w0.65: v1(3.3,13) v1(3.3,13.6) 2.778,14.122 2.778,16.778 3.4,17.4 3.4,22.4 4.2,23.2 v1(4.8,23.2) v1(5.5,23.2)
  Bottom Layer w0.65: v1(3.3,13.6) v1(3.3,13) 3.325,12.975 R211.1@4.4,12.975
